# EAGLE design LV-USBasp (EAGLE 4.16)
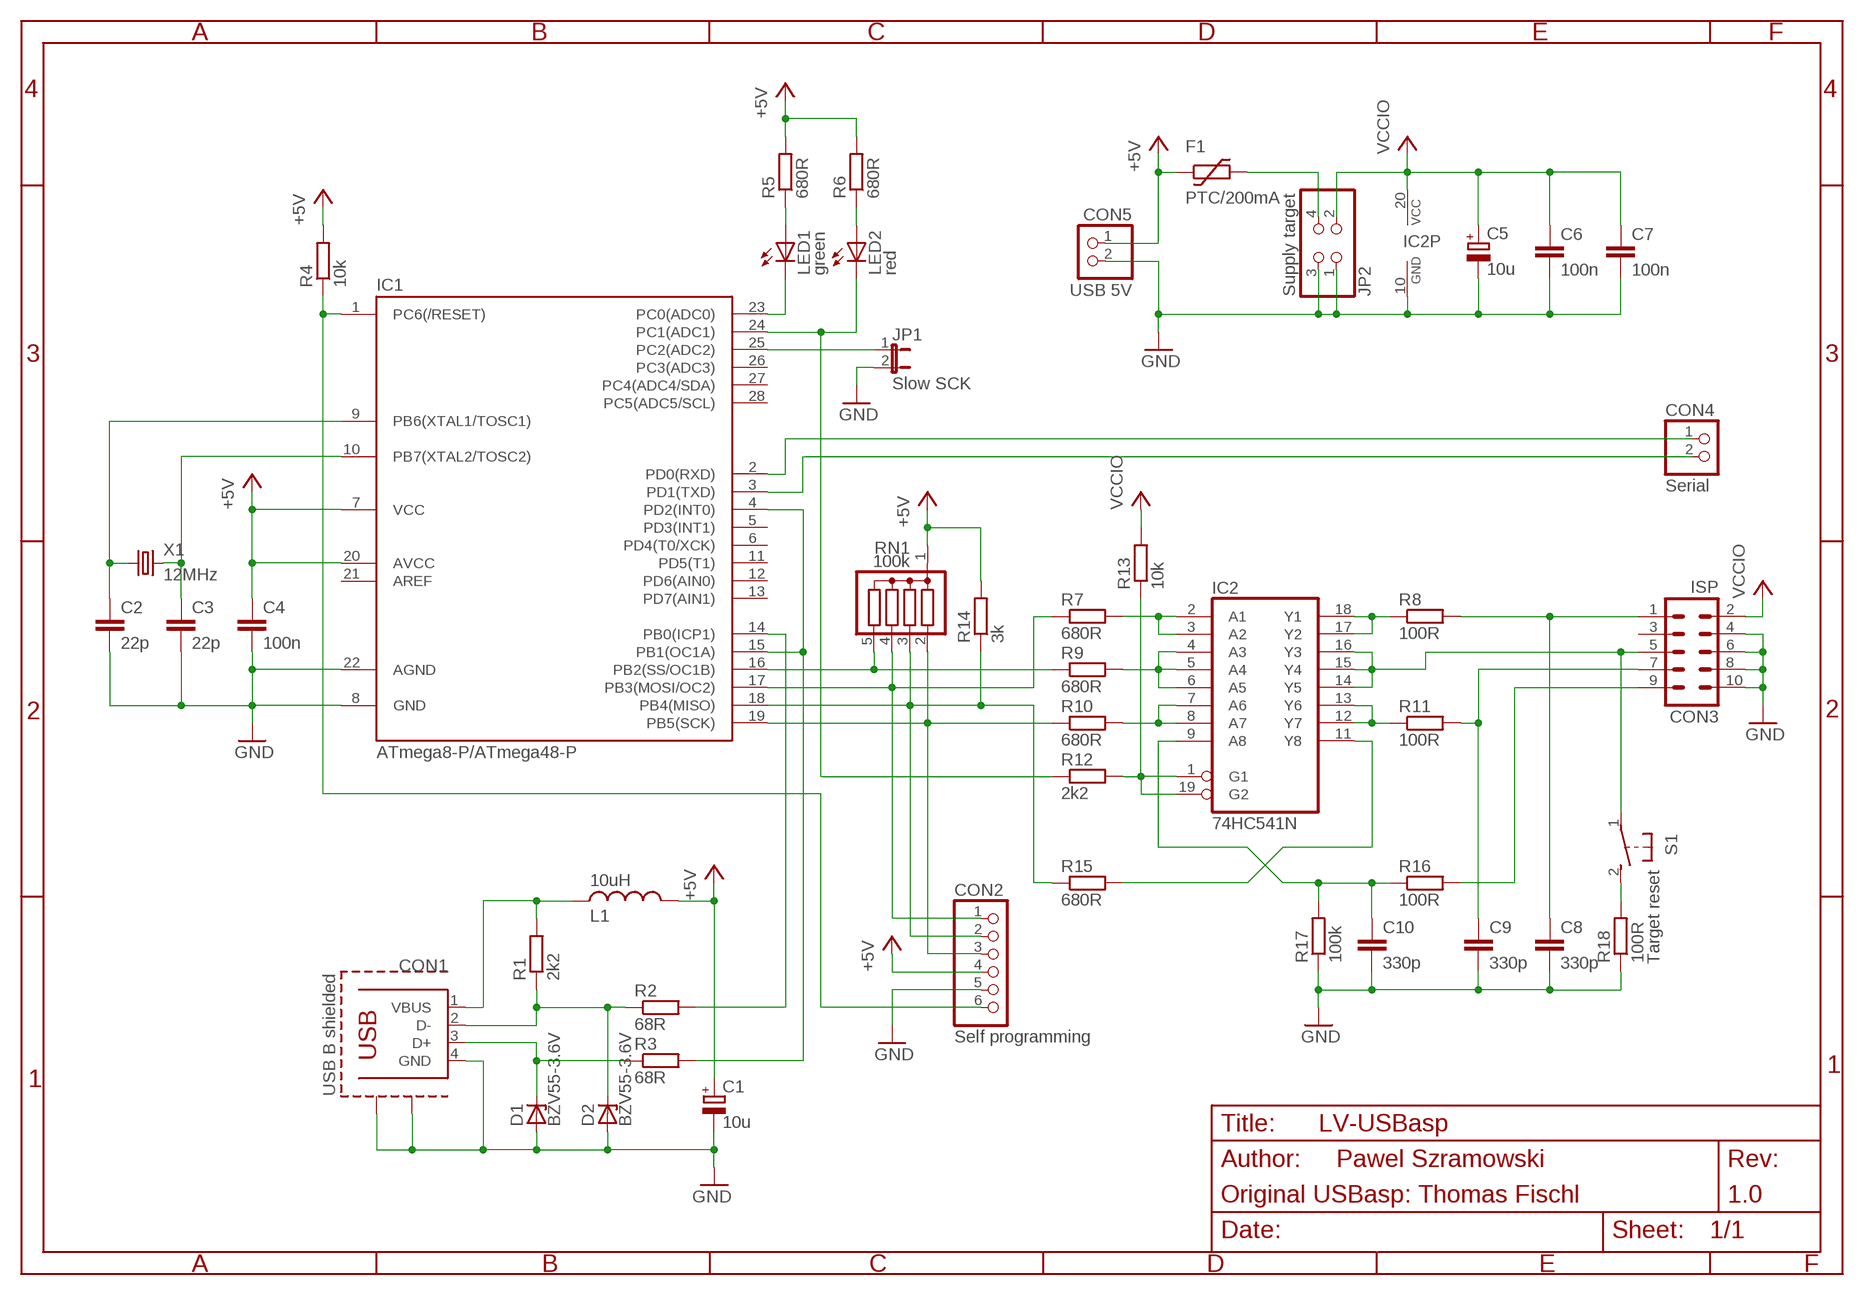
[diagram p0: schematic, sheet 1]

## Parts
C1  10u  CPOL-EUE2-5  [E2-5]
C2  22p  C-EUC1206  [C1206]
C3  22p  C-EUC1206  [C1206]
C4  100n  C-EUC1206  [C1206]
C5  10u  CPOL-EUE2-5  [E2-5]
C6  100n  C-EUC1206  [C1206]
C7  100n  C-EUC1206  [C1206]
C8  330p  C-EUC1206  [C1206]
C9  330p  C-EUC1206  [C1206]
C10  330p  C-EUC1206  [C1206]
CON1  USB B shielded  USB_B_SHIELDED  [USB_B_SHIELDED_THMD]
CON2  Self programming  PINHD-1X6  [1X06]
CON3  ISP  ML10  [ML10]
CON4  Serial  PINHD-1X2  [1X02]
CON5  USB 5V  PINHD-1X2  [1X02]
D1  BZV55-3.6V  ZENER-DIODESOD80C  [SOD80C]
D2  BZV55-3.6V  ZENER-DIODESOD80C  [SOD80C]
F1  PTC/200mA  PPTC-MINI_SMD_C  [MINI_SMD_C]
IC1  ATmega8-P/ATmega48-P  ATMEGA8-P  [DIL28-3]
IC2  74HC541N  [DIL20]
JP1  Slow SCK  JP1E  [JP1]
JP2  Supply target  PINHD-2X2  [2X02]
L1  10uH  L-US0207/10  [0207/10]
LED1  green  LED3MM  [LED3MM]
LED2  red  LED3MM  [LED3MM]
R1  2k2  R-EU_R1206  [R1206]
R2  68R  R-EU_R1206  [R1206]
R3  68R  R-EU_R1206  [R1206]
R4  10k  R-EU_R1206  [R1206]
R5  680R  R-EU_R1206  [R1206]
R6  680R  R-EU_R1206  [R1206]
R7  680R  R-EU_R1206  [R1206]
R8  100R  R-EU_R1206  [R1206]
R9  680R  R-EU_R1206  [R1206]
R10  680R  R-EU_R1206  [R1206]
R11  100R  R-EU_R1206  [R1206]
R12  2k2  R-EU_R1206  [R1206]
R13  10k  R-EU_R1206  [R1206]
R14  3k  R-EU_R1206  [R1206]
R15  680R  R-EU_R1206  [R1206]
R16  100R  R-EU_R1206  [R1206]
R17  100k  R-EU_R1206  [R1206]
R18  100R  R-EU_R1206  [R1206]
RN1  100k  G04R  [SIL5]
S1  Target reset  DTS-3  [DTS-3]
X1  12MHz  CRYSTALHC49S  [HC49/S]

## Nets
+5V: C1.+ C4.1 CON2.4 CON5.1 F1.1 IC1.7(VCC) IC1.20(AVCC) L1.1 R4.2 R5.2 R6.2 R14.2 RN1.1
/RST: CON2.6 IC1.1(PC6(/RESET)) R4.1
GND: C1.- C2.2 C3.2 C4.2 C5.- C6.2 C7.2 C8.2 C9.2 C10.2 CON1.4(GND) CON1.S1 CON1.S2 CON2.5 CON3.4 CON3.6 CON3.8 CON3.10 CON5.2 D1.A D2.A IC1.8(GND) IC1.22(AGND) IC2.10(GND) JP1.2 JP2.1 JP2.3 R17.1 R18.1
MISO: CON2.2 IC1.18(PB4(MISO)) R14.1 R15.1 RN1.3
MOSI: CON2.1 IC1.17(PB3(MOSI/OC2)) R7.1 RN1.4
N$1: C3.1 IC1.10(PB7(XTAL2/TOSC2)) X1.2
N$2: IC1.25(PC2(ADC2)) JP1.1
N$3: F1.2 JP2.4
N$4: IC1.24(PC1(ADC1)) LED2.K(C) R12.1
N$5: IC1.23(PC0(ADC0)) LED1.K(C)
N$6: CON1.3(D+) D1.C R3.1
N$7: CON1.2(D-) D2.C R1.1 R2.1
N$8: LED1.A R5.1
N$9: LED2.A R6.1
N$10: IC1.14(PB0(ICP1)) R2.2
N$11: R18.2 S1.2
N$13: C2.1 IC1.9(PB6(XTAL1/TOSC1)) X1.1
N$19: IC2.2(A1) IC2.3(A2) R7.2
N$20: IC1.4(PD2(INT0)) IC1.15(PB1(OC1A)) R3.2
N$21: IC1.16(PB2(SS/OC1B)) R9.1 RN1.5
N$22: C10.1 IC2.9(A8) R16.1 R17.2
N$23: C9.1 CON3.7 R11.2
N$24: C8.1 CON3.1 R8.2
N$25: CON3.9 R16.2
N$27: IC2.4(A3) IC2.5(A4) IC2.6(A5) R9.2
N$28: IC2.7(A6) IC2.8(A7) R10.2
N$29: IC2.17(Y2) IC2.18(Y1) R8.1
N$30: CON3.5 IC2.14(Y5) IC2.15(Y4) IC2.16(Y3) S1.1
N$31: IC2.12(Y7) IC2.13(Y6) R11.1
N$32: IC2.1(G1) IC2.19(G2) R12.2 R13.1
N$33: IC2.11(Y8) R15.2
RXD: CON4.1 IC1.2(PD0(RXD))
SCK: CON2.3 IC1.19(PB5(SCK)) R10.1 RN1.2
TXD: CON4.2 IC1.3(PD1(TXD))
VBUS: CON1.1(VBUS) L1.2 R1.2
VCCIO: C5.+ C6.1 C7.1 CON3.2 IC2.20(VCC) JP2.2 R13.2
Unconnected: CON3.3 IC1.5(PD3(INT1)) IC1.6(PD4(T0/XCK)) IC1.11(PD5(T1)) IC1.12(PD6(AIN0)) IC1.13(PD7(AIN1)) IC1.21(AREF) IC1.26(PC3(ADC3)) IC1.27(PC4(ADC4/SDA)) IC1.28(PC5(ADC5/SCL))

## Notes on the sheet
- Pawel Szramowski
- Original USBasp: Thomas Fischl | 1.0

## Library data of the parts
C1 C5 = rcl:CPOL-EU: POLARIZED CAPACITOR, European symbol
C2-C4 C6-C10 = rcl:C-EU: CAPACITOR, European symbol
CON1 = USB:USB_B_SHIELDED
CON2 = pinhead:PINHD-1X6: PIN HEADER
CON3 = con-harting-ml:ML10: HARTING
CON4 CON5 = pinhead:PINHD-1X2: PIN HEADER
D1 D2 = diode:ZENER-DIODE: Z-Diode
F1 = PolySwitch_SMD:PPTC: PTC symbol
IC1 = ATmega8:ATMEGA8-P
IC2 = 74xx-eu:74*541: Octal BUFFER and LINE DRIVER, 3-state
JP1 = jumper:JP1E: JUMPER
JP2 = pinhead:PINHD-2X2: PIN HEADER
L1 = rcl:L-US: INDUCTOR, American symbol
LED1 LED2 = led:LED: LED
R1-R18 = rcl:R-EU_: RESISTOR, European symbol
RN1 = resistor-sil:G04R: SIL RESISTOR
S1 = switch-tact:DTS-3
X1 = crystal:CRYSTAL: CRYSTAL

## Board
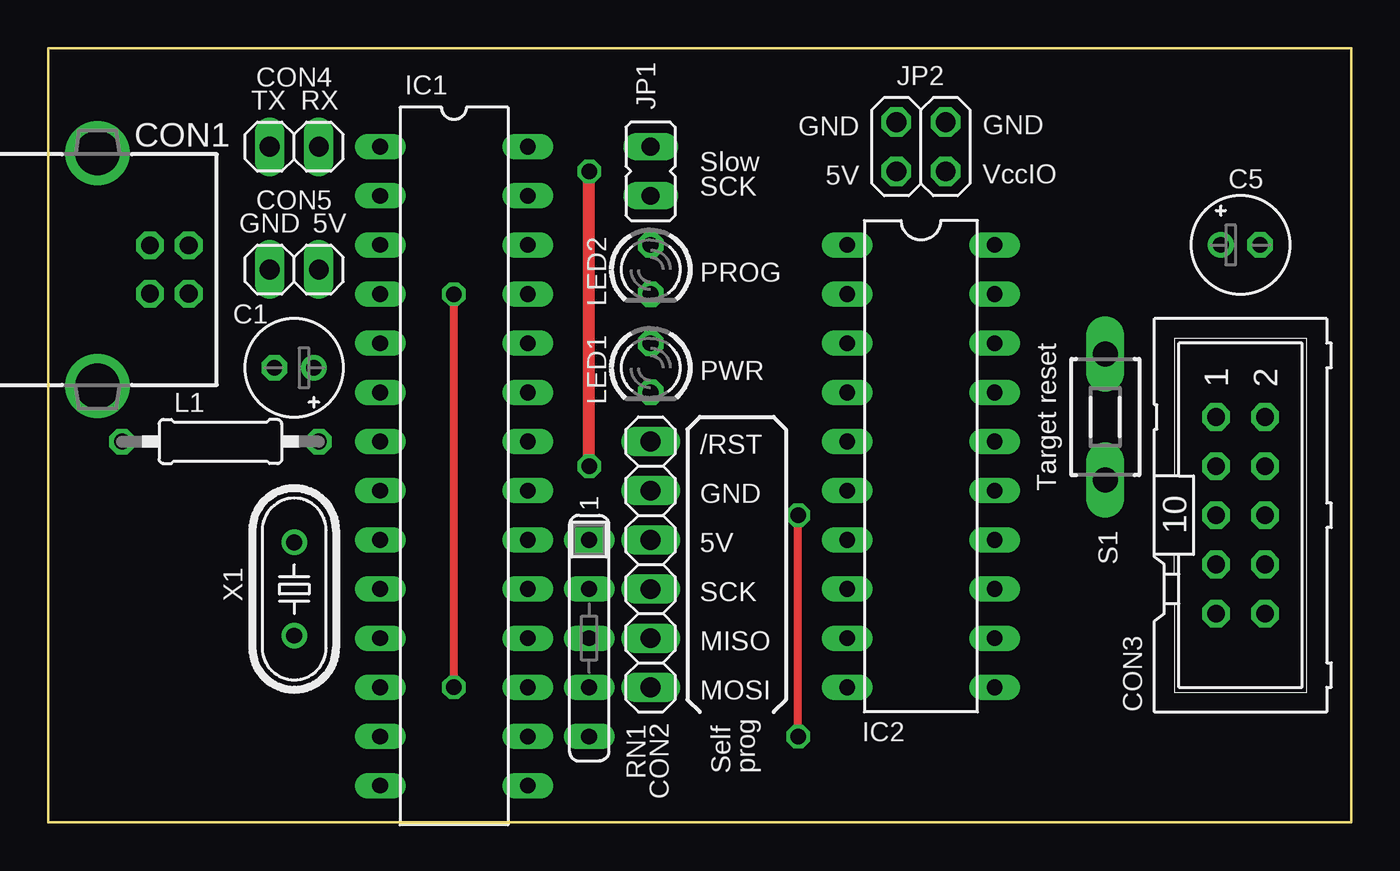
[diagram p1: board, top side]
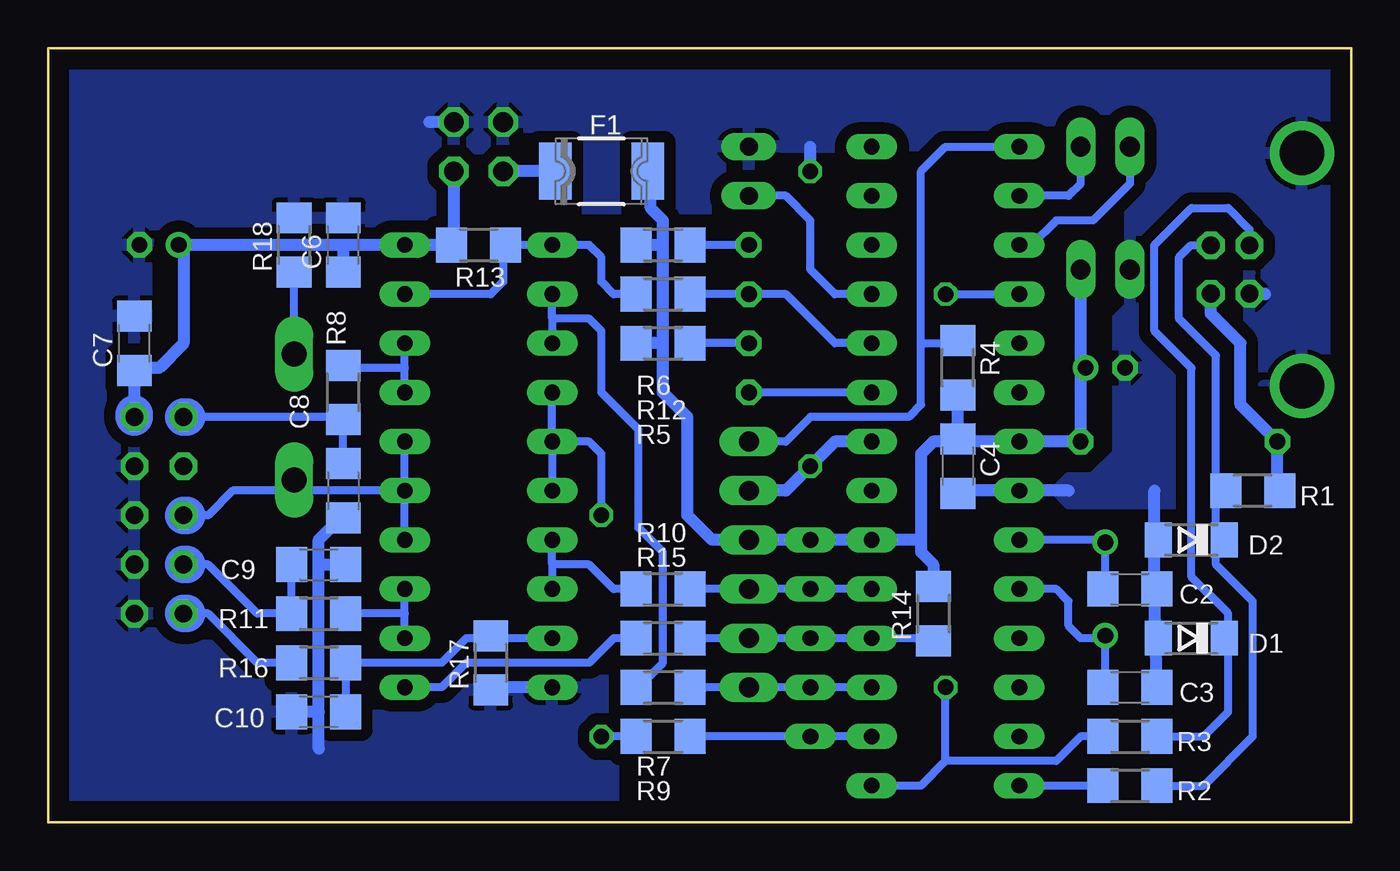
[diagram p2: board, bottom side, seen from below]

Size 67.31 x 40.01 mm. Coordinates in mm from the lower left corner, seen from the top.
Outline: 0,0 67.31,0 67.31,40.01 0,40.01 0,0
Copper layers (1*16): Top 0.035mm / dielectric 1.5mm / Bottom 0.035mm
Design rules "default": minimum track width 10mil, minimum drill 24mil, track to track 8mil, track to pad 8mil, pad to pad 8mil, via to via 8mil, smd to smd 8mil, copper to edge 40mil, drill to drill 8mil, minimum pad ring 10mil, minimum via ring 8mil, stop-mask expansion 4mil, vias tented up to drill 0mil, thermal gap 10mil

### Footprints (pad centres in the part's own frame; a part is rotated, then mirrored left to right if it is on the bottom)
E2-5 = drill 0.813 pad 1.27 round: + -1.016,0 | drill 0.813 pad 1.27 octagon: - 1.016,0
C1206 = smd 1.6 x 1.8: 1 -1.4,0; 2 1.4,0
USB_B_SHIELDED_THMD = drill 0.92 octagon: 1 4.71,-1.25; 2 4.71,1.25; 3 2.71,1.25; 4 2.71,-1.25 | drill 2.3 round: S1 0,6.02; S2 0,-6.02
1X06 = drill 1.016 long: 1 -6.35,0; 2 -3.81,0; 3 -1.27,0; 4 1.27,0; 5 3.81,0; 6 6.35,0
ML10 = drill 0.914 octagon: 1 -5.08,-1.27; 2 -5.08,1.27; 3 -2.54,-1.27; 4 -2.54,1.27; 5 0,-1.27; 6 0,1.27; 7 2.54,-1.27; 8 2.54,1.27; 9 5.08,-1.27; 10 5.08,1.27
1X02 = drill 1.016 long: 1 -1.27,0; 2 1.27,0
SOD80C = smd 1.4 x 1.8: A 1.7,0; C -1.7,0
MINI_SMD_C = smd 1.68 x 2.95: 1 -2.39,0; 2 2.39,0
DIL28-3 = drill 0.813 long: 1 -16.51,-3.81; 2 -13.97,-3.81; 3 -11.43,-3.81; 4 -8.89,-3.81; 5 -6.35,-3.81; 6 -3.81,-3.81; 7 -1.27,-3.81; 8 1.27,-3.81; 9 3.81,-3.81; 10 6.35,-3.81; 11 8.89,-3.81; 12 11.43,-3.81; 13 13.97,-3.81; 14 16.51,-3.81; 15 16.51,3.81; 16 13.97,3.81; 17 11.43,3.81; 18 8.89,3.81; 19 6.35,3.81; 20 3.81,3.81; 21 1.27,3.81; 22 -1.27,3.81; 23 -3.81,3.81; 24 -6.35,3.81; 25 -8.89,3.81; 26 -11.43,3.81; 27 -13.97,3.81; 28 -16.51,3.81
DIL20 = drill 0.813 long: 1 -11.43,-3.81; 2 -8.89,-3.81; 3 -6.35,-3.81; 4 -3.81,-3.81; 5 -1.27,-3.81; 6 1.27,-3.81; 7 3.81,-3.81; 8 6.35,-3.81; 9 8.89,-3.81; 10 11.43,-3.81; 11 11.43,3.81; 12 8.89,3.81; 13 6.35,3.81; 14 3.81,3.81; 15 1.27,3.81; 16 -1.27,3.81; 17 -3.81,3.81; 18 -6.35,3.81; 19 -8.89,3.81; 20 -11.43,3.81
JP1 = drill 0.914 long: 1 0,-1.27; 2 0,1.27
2X02 = drill 1.016 octagon: 1 -1.27,-1.27; 2 -1.27,1.27; 3 1.27,-1.27; 4 1.27,1.27
0207/10 = drill 0.813 octagon: 1 -5.08,0; 2 5.08,0
LED3MM = drill 0.813 octagon: A -1.27,0; K 1.27,0
R1206 = smd 1.6 x 1.8: 1 -1.4,0; 2 1.4,0
SIL5 = drill 0.813 long: 1 -5.08,0; 2 -2.54,0; 3 0,0; 4 2.54,0; 5 5.08,0
DTS-3 = drill 1.3 long: 1 -3.25,0; 2 3.25,0
HC49/S = drill 0.813 round: 1 -2.413,0; 2 2.413,0

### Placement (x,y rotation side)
C1  12.7,23.5 180 top
C2  11.43,12.06 0 bottom
C3  11.43,6.99 0 bottom
C4  20.32,18.41 270 bottom
C5  61.59,29.84 0 top
C6  52.07,29.84 90 bottom
C7  62.87,24.77 90 bottom
C8  52.07,17.14 270 bottom
C9  53.34,13.34 0 bottom
C10  53.34,5.71 180 bottom
CON1  2.54,28.57 0 top
CON2  31.11,13.34 90 top
CON3  61.59,15.88 270 top
CON4  12.7,34.92 180 top
CON5  12.7,28.57 180 top
D1  8.26,9.53 180 bottom
D2  8.26,14.61 180 bottom
F1  38.73,33.66 180 bottom
IC1  20.95,18.41 270 top
IC2  45.09,18.41 270 top
JP1  31.11,33.66 0 top
JP2  45.09,34.92 180 top
L1  8.89,19.68 180 top
LED1  31.11,23.5 270 top
LED2  31.11,28.57 270 top
R1  5.08,17.14 0 bottom
R2  11.43,1.91 180 bottom
R3  11.43,4.45 180 bottom
R4  20.32,23.5 270 bottom
R5  35.56,24.77 180 bottom
R6  35.56,29.84 180 bottom
R7  35.56,6.99 180 bottom
R8  52.07,22.23 270 bottom
R9  35.56,4.45 180 bottom
R10  35.56,12.06 180 bottom
R11  53.34,10.79 180 bottom
R12  35.56,27.3 180 bottom
R13  45.09,29.84 180 bottom
R14  21.59,10.79 90 bottom
R15  35.56,9.53 180 bottom
R16  53.34,8.26 180 bottom
R17  44.45,8.26 90 bottom
R18  54.61,29.84 270 bottom
RN1  27.94,9.53 270 top
S1  54.61,20.95 90 top
X1  12.7,12.06 270 top

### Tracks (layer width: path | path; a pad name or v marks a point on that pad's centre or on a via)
+5V
  Bottom 0.61: 20.32,19.68 IC1.7 L1.1 13.97,23.5 | R4.2 C4.1 20.32,19.68 | 22.23,14.61 IC1.20 RN1.1 CON2.4 33.02,14.61 34.29,15.88 34.29,20.95 35.56,22.23 35.56,24.77 | 22.23,14.61 22.23,19.05 21.59,19.68 20.32,19.68 | 35.56,24.77 35.56,29.84 | 35.56,29.84 R6.2 | 35.56,24.77 R5.2 | 22.23,14.61 22.23,13.97 21.59,13.34 R14.2 21.59,12.06 | 13.97,23.5 CON5.1 | 13.97,23.5 C1.+ | 35.56,29.84 35.56,31.11 36.2,31.75 36.2,33.66 F1.1
/RST
  Bottom 0.406: IC1.1 20.95,34.92 22.23,33.66 22.23,24.77 | CON2.6 29.21,19.68 27.94,20.95 22.86,20.95 22.23,21.59 22.23,24.77 | R4.1 20.32,24.77 22.23,24.77
GND  (via drill 0.8)
  Top 0.61: v27.94,18.41 v27.94,33.66
  Bottom 0.61: CON2.5 29.21,17.14 v27.94,18.41 26.67,19.68 IC1.22 | 53.34,3.81 53.34,5.71 | 53.34,5.71 53.34,13.34 | 53.34,13.34 53.34,14.61 52.07,15.88 C8.2 | 53.34,5.71 C10.2 | 53.34,13.34 C9.2 | C4.2 20.32,17.14 IC1.8 14.61,17.14 | R17.1 43.81,6.99 | 10.16,12.06 10.16,9.53 D1.A | 10.16,12.06 10.16,14.61 | C3.2 10.16,12.06 | 10.16,12.06 C2.2 | C1.- 11.43,23.5 | 10.16,14.61 D2.A | 10.16,14.61 10.16,17.14 | 4.45,27.3 4.46,27.32 | IC2.10 44.45,6.99 | JP2.1 47.62,36.2 | v27.94,33.66 27.94,34.92
  pour Bottom (isolate 0.61): 0.64,39.37 66.67,39.37 66.67,0.64 38.1,0.64 38.1,8.26 38.73,8.26 40.01,6.99 55.24,6.99 55.88,7.62 56.52,7.62 59.69,10.79 62.87,10.79 62.87,24.77 62.23,25.4 62.23,29.84 61.59,30.48 46.99,30.48 46.99,31.75 31.11,31.75 31.11,34.92 11.43,34.92 11.43,26.67 12.06,26.04 12.06,19.05 13.34,17.78 14.61,17.78 15.24,17.14 14.61,16.51 8.89,16.51 8.89,22.86 0.64,22.86
MISO
  Bottom 0.406: 34.29,9.53 R15.1 CON2.2 RN1.3 IC1.18 21.59,9.53 R14.1
MOSI
  Bottom 0.406: IC1.17 RN1.4 CON2.1 R7.1 34.29,6.99
N$1
  Bottom 0.406: IC1.10 15.24,12.06 14.61,11.43 14.61,10.16 13.97,9.53 12.7,9.53 X1.2 12.7,6.99 C3.1
N$2
  Bottom 0.406: IC1.25 26.67,27.3 27.94,28.57 27.94,31.11 29.21,32.38 JP1.1
N$3
  Bottom 0.61: F1.2 JP2.4
N$4
  Bottom 0.406: IC1.24 26.67,24.77 29.21,27.3 LED2.K R12.1 34.29,27.3
N$5
  Bottom 0.406: IC1.23 LED1.K
N$6
  Bottom 0.406: R3.1 7.62,4.45 6.35,5.71 6.35,9.53 | 6.35,9.53 D1.C | 6.35,9.53 6.35,10.79 8.26,12.7 8.26,23.5 10.16,25.4 10.16,29.84 8.26,31.75 6.35,31.75 5.25,30.65 CON1.3
N$7
  Bottom 0.406: 6.99,14.61 6.99,13.34 5.08,11.43 5.08,4.45 7.62,1.91 R2.1 10.16,1.91 | 6.99,14.61 6.99,17.14 | 6.99,17.14 6.99,24.13 8.89,26.04 8.89,29.21 8.28,29.82 CON1.2 | 6.99,14.61 D2.C | 6.99,17.14 R1.1
N$8
  Bottom 0.406: 34.29,24.77 R5.1 LED1.A
N$9
  Bottom 0.406: 34.29,29.84 R6.1 LED2.A
N$10
  Bottom 0.406: 12.7,1.91 R2.2 IC1.14
N$11
  Bottom 0.406: 54.61,24.13 S1.2 R18.2
N$13
  Bottom 0.406: IC1.9 12.7,14.61 X1.1 12.7,12.06 C2.1
N$19
  Bottom 0.406: 41.27,26.04 IC2.3 | 41.27,26.04 IC2.2 | 41.27,26.04 39.37,26.04 38.73,25.4 38.73,22.23 36.83,20.32 36.83,15.24 35.56,13.97 35.56,8.26 36.83,6.99 R7.2
N$20  (via drill 0.8)
  Top 0.406: v20.95,6.99 v20.95,27.3
  Bottom 0.406: IC1.15 22.23,1.91 20.95,3.17 | v20.95,27.3 IC1.4 | 20.95,3.17 v20.95,6.99 | R3.2 13.97,4.45 15.24,3.17 20.95,3.17
N$21
  Bottom 0.406: IC1.16 RN1.5 R9.1 34.29,4.45
N$22
  Bottom 0.406: IC2.9 43.81,9.53 | 43.81,9.53 45.72,9.53 46.99,8.26 R16.1 | R16.1 52.07,8.26 | C10.1 52.07,5.71 51.94,5.84 R16.1 | 43.81,9.53 R17.2
N$23
  Bottom 0.406: 60.17,13.34 59.05,13.34 56.52,10.79 R11.2 | R11.2 54.61,10.79 | C9.1 54.61,13.34 54.74,13.21 R11.2
  Bottom 1.93: 60.17,13.34 CON3.7
N$24
  Bottom 0.406: 60.17,20.95 52.07,20.95 R8.2 C8.1
  Bottom 1.93: 60.17,20.95 CON3.1
N$25
  Bottom 0.406: 60.17,10.79 59.05,10.79 56.52,8.26 R16.2 54.61,8.26
  Bottom 1.93: 60.17,10.79 CON3.9
N$27  (via drill 0.8)
  Top 0.406: v38.73,4.45 v38.73,15.88
  Bottom 0.406: IC2.5 IC2.4 | IC2.5 IC2.6 | R9.2 v38.73,4.45 | v38.73,15.88 38.73,19.05 39.37,19.68 IC2.5
N$28
  Bottom 0.406: 41.27,13.34 IC2.8 | 41.27,13.34 IC2.7 | 41.27,13.34 39.37,13.34 38.1,12.06 R10.2 36.83,12.06
N$29
  Bottom 0.406: IC2.17 48.9,23.5 | 48.9,23.5 IC2.18 | R8.1 52.07,23.5 48.9,23.5
N$30
  Bottom 0.406: IC2.15 IC2.16 | IC2.14 IC2.15 | IC2.15 54.61,17.14 | 54.61,17.14 57.78,17.14 59.05,15.88 60.17,15.88 | 54.61,17.14 S1.1
  Bottom 1.93: 60.17,15.88 CON3.5
N$31
  Bottom 0.406: IC2.12 48.9,10.79 | 48.9,10.79 IC2.13 | 52.07,10.79 R11.1 48.9,10.79
N$32
  Bottom 0.406: 36.83,27.3 R12.2 38.1,27.3 38.73,27.94 38.73,29.21 39.37,29.84 IC2.1 R13.1 43.81,29.84 43.81,27.94 44.45,27.3 IC2.19
N$33
  Bottom 0.406: IC2.11 46.99,6.99 45.72,8.26 39.37,8.26 38.1,9.53 R15.2 36.83,9.53
RXD
  Bottom 0.406: IC1.2 14.61,32.38 13.97,33.02 CON4.1
SCK
  Bottom 0.406: IC1.19 RN1.2 CON2.3 R10.1 34.29,12.06
TXD
  Bottom 0.406: IC1.3 16.51,29.84 15.24,31.11 13.34,31.11 11.43,33.02 CON4.2
VBUS
  Bottom 0.61: 6.35,25.4 5.71,24.77 5.71,21.59 L1.2 3.81,17.14 R1.2 | 6.35,25.4 6.62,25.66 | CON1.1 7.25,26.3 6.35,25.4
VCCIO
  Bottom 0.61: 62.87,21.11 C7.1 62.87,23.5 61.59,23.5 60.33,24.77 60.33,29.84 | 52.07,29.84 IC2.20 R13.2 46.35,29.84 JP2.2 | 52.07,29.84 60.33,29.84 | 60.33,29.84 C5.+ | 52.07,29.84 C6.1
  Bottom 1.93: 62.87,21.11 CON3.2

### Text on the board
tPlace: TX | RX | GND | GND | Slow | 5V | VccIO | SCK | GND | 5V | PROG | PWR | /RST | GND | Target reset | 5V | SCK | MISO | MOSI | Self | prog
